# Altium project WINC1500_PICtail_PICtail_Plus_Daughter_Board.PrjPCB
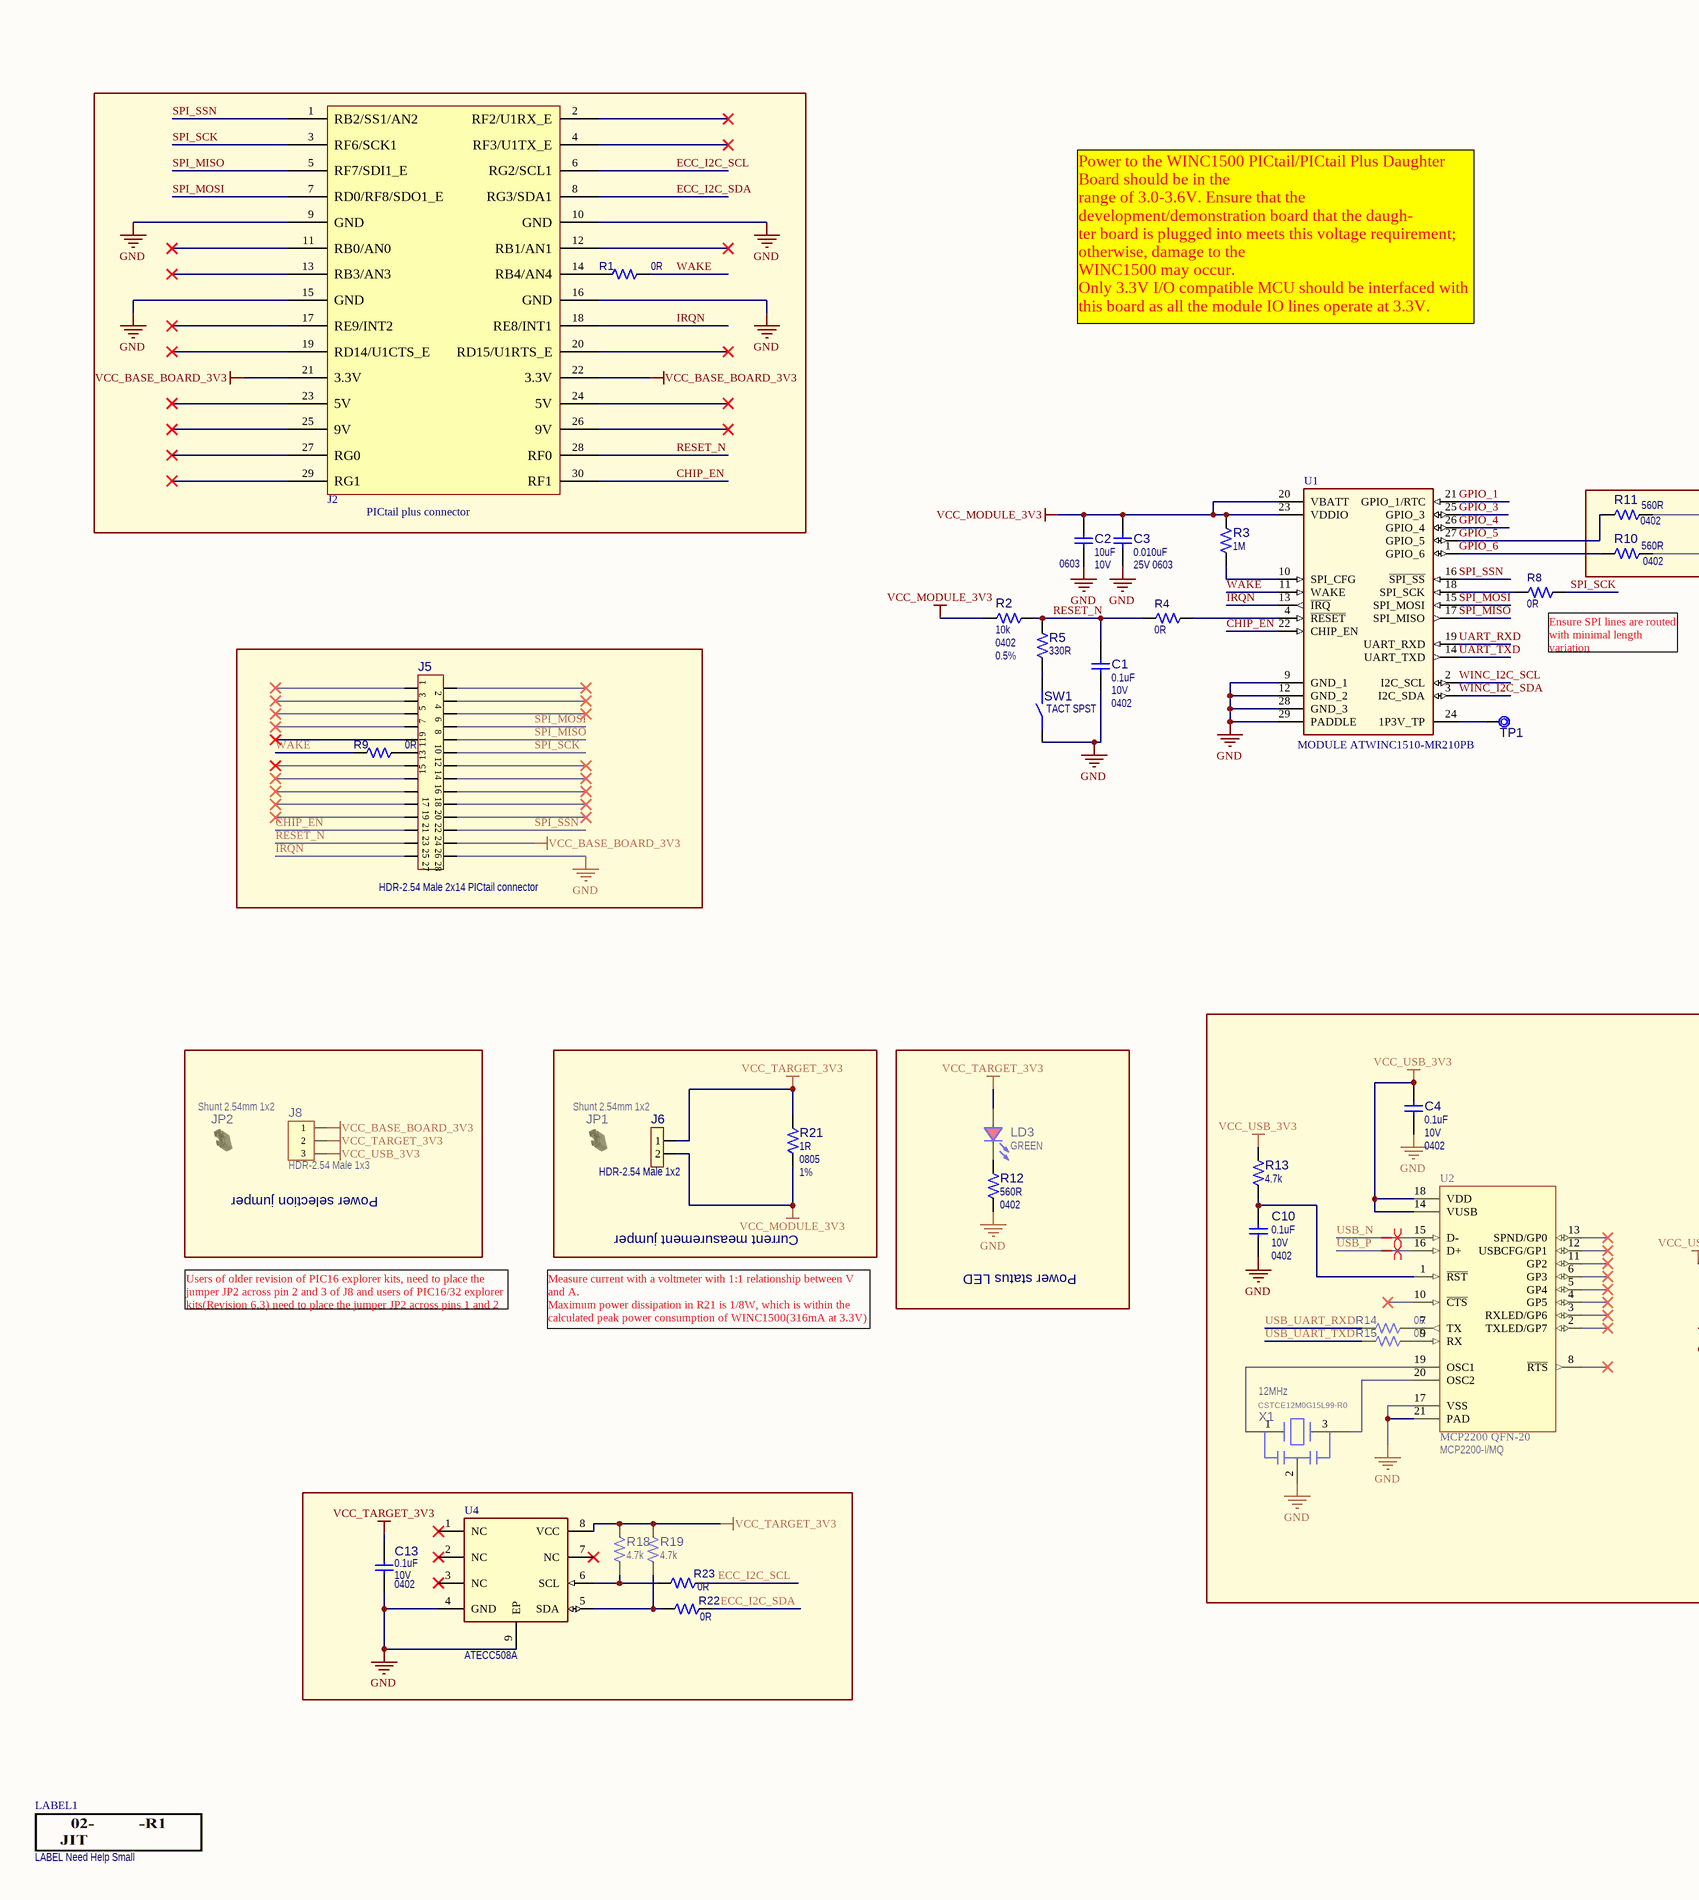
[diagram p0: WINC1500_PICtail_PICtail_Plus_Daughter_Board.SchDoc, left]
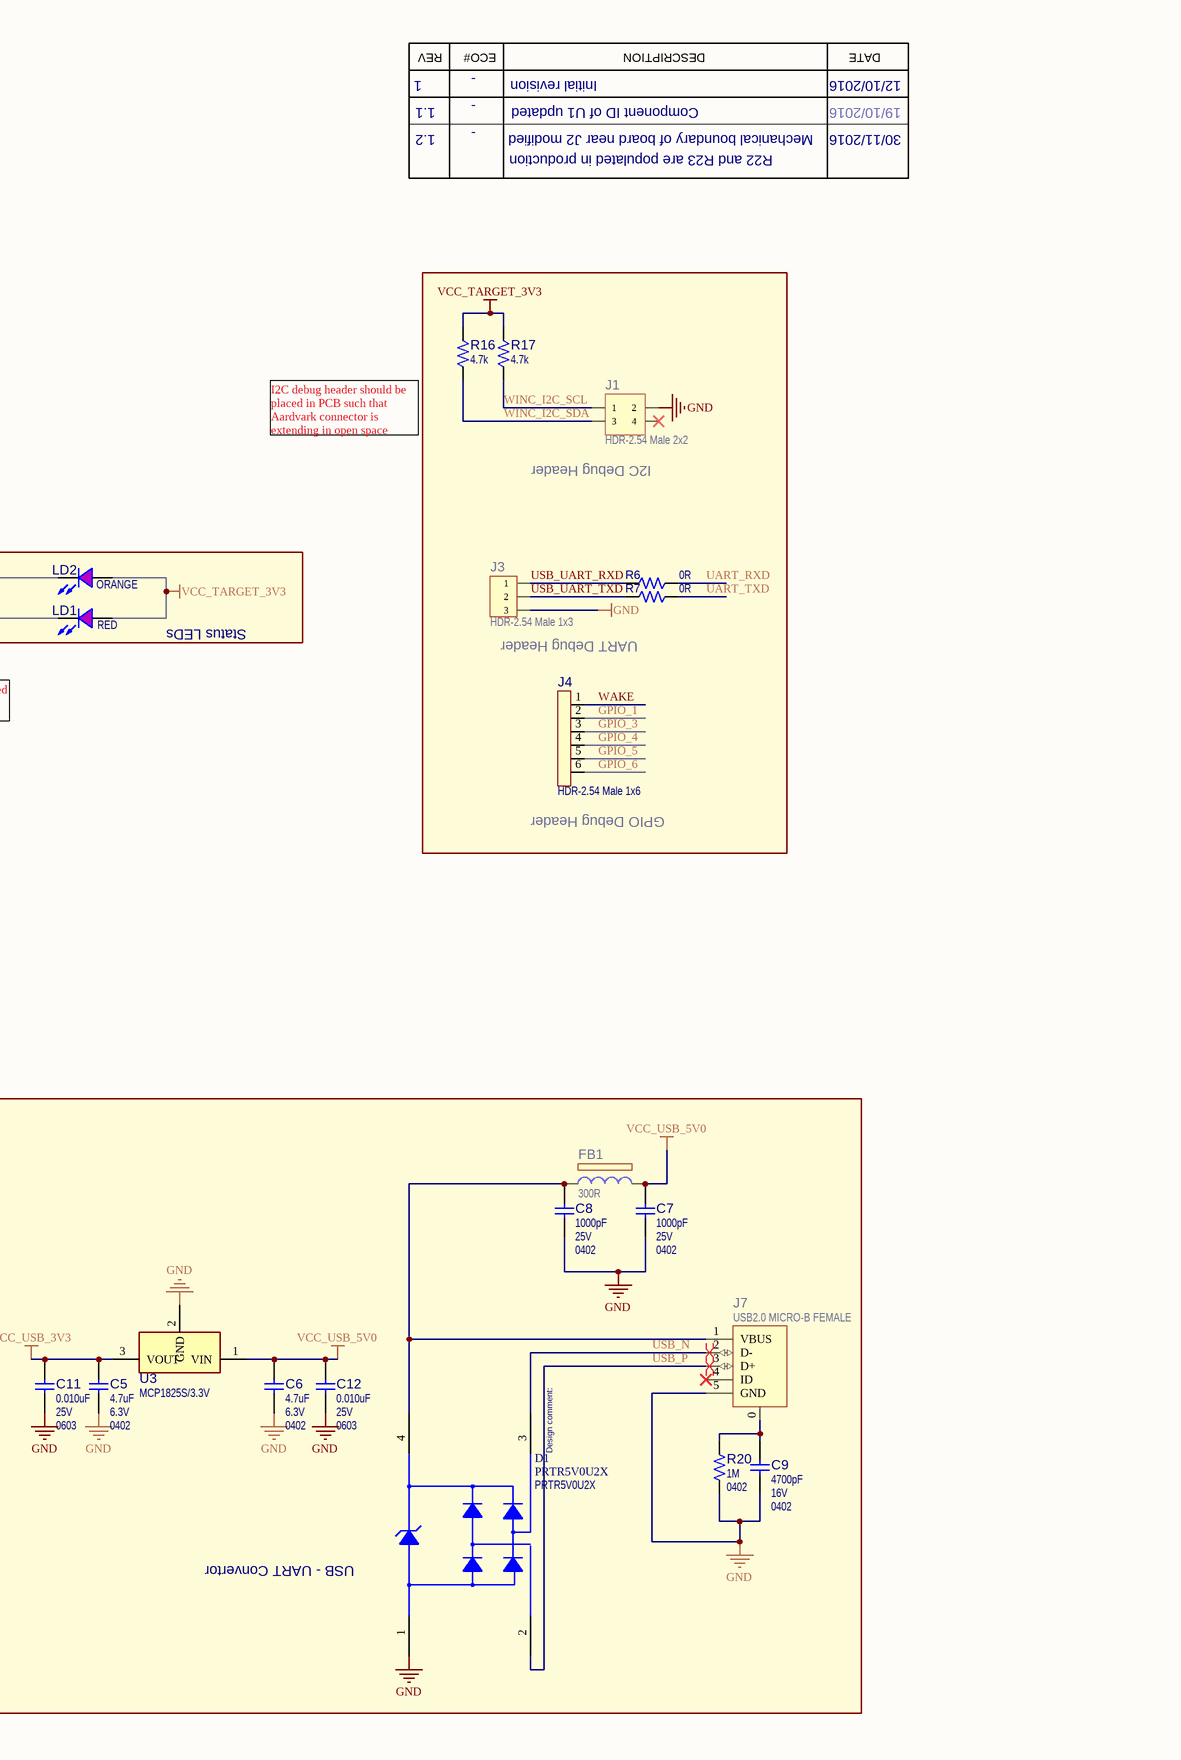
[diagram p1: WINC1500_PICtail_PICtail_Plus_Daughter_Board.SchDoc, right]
ProjectTitle: WINC1500 PICtail/PICtail Plus Daughter Board; ProjectRevisionSCH: 1.2; ProjectRevisionFAB: 1.2; ProjectRevisionASSY: 1.2; ProjectRevisionART: 1.2; ProjectPartNumber: AC164156; ProjectEngineer: Arun karthik; ProjectDrawnBy: Arun karthik; ProjectBoardNumber: 10608
1 sheet, 60 parts. Net scope: global (net labels, ports and power ports of the same name join across sheets).
Board file: WINC1500_PICtail_PICtail_Plus_Daughter_Board.PcbDoc

## Sheet WINC1500_PICtail_PICtail_Plus_Daughter_Board.SchDoc: WINC1500 PICtail
size C; Author: Arun karthik; CompanyName: Microchip Technology Inc.; DrawnBy: Arun karthik; Engineer: Arun karthik; Organization: Microchip Technology; Address1: 2355 West Chandler Blvd.; Address2: Chandler, AZ  85224; Address4: USA; DocumentNumber: 1; Revision: 1.2; SheetNumber: 1; SheetTotal: 1; SheetTitle: WINC1500 PICtail; ProjectDrawnby: Arun karthik; ProjectEngineer: Arun karthik; ProjectRevisionSCH: 1.2; ProjectBoardNumber: 10608; ProjectPartNumber: AC164156; ProjectTitle: WINC1500 PICtail/PICtail Plus Board

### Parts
?  (no value)  (graphical)
C1  value 0.1uF  Voltage: 10V  Package: 0402  [CAP_C_0402]  (hidden comment: Capacitor NP)
C2  value 10uF  Voltage: 10V  Package: 0603  [CAP_C_0603]  (hidden comment: Capacitor NP)
C3  value 0.010uF  Voltage: 25V  Package: 0603  [CAP_C_0603]  (hidden comment: Capacitor NP)
C4  value 0.1uF  Voltage: 10V  Package: 0402  [CAP_C_0402]  (hidden comment: Capacitor NP)
C5  value 4.7uF  Voltage: 6.3V  Package: 0402  [CAP_C_0402]  (hidden comment: Capacitor NP)
C6  value 4.7uF  Voltage: 6.3V  Package: 0402  [CAP_C_0402]  (hidden comment: Capacitor NP)
C7  value 1000pF  Voltage: 25V  Package: 0402  [CAP_C_0402]  (hidden comment: Capacitor NP)
C8  value 1000pF  Voltage: 25V  Package: 0402  [CAP_C_0402]  (hidden comment: Capacitor NP)
C9  value 4700pF  Voltage: 16V  Package: 0402  [CAP_C_0402]  (hidden comment: Capacitor NP)
C10  value 0.1uF  Voltage: 10V  Package: 0402  [CAP_C_0402]  (hidden comment: Capacitor NP)
C11  value 0.010uF  Voltage: 25V  Package: 0603  [CAP_C_0603]  (hidden comment: Capacitor NP)
C12  value 0.010uF  Voltage: 25V  Package: 0603  [CAP_C_0603]  (hidden comment: Capacitor NP)
C13  value 0.1uF  Voltage: 10V  Package: 0402  [CAP_C_0402]  (hidden comment: Capacitor NP)
D1  PRTR5V0U2X  [SOT-143]
FB1  value 300R  [IND_C_0805]  (hidden comment: Ferrite Bead)
J1  value HDR-2.54 Male 2x2  [HDR_M_2.54_2x2]  (hidden comment: Header 2x2)
J2  PICtail plus connector  [CON_EDGE-CARD_PCB_RA_PICTAIL_PLUS_30A_Alternate1]  (no BOM)
J3  value HDR-2.54 Male 1x3  [HDR_M_2.54_1x3]  (hidden comment: Header 1x3)
J4  value HDR-2.54 Male 1x6  [HDR_M_2.54_1x6]  (hidden comment: Header 1x6)
J5  value HDR-2.54 Male 2x14 PICtail connector  [HDR_M_2.54_2x14_RA]  (hidden comment: Header 2x14)
J6  value HDR-2.54 Male 1x2  [HDR_M_2.54_1x2]  (hidden comment: Header 1x2)
J7  value USB2.0 MICRO-B FEMALE  [CON_USB_Micro-AB_SMD_TH_RA_FCI_10118194-0001LF]  (hidden comment: CON USB2.0 Mini_Micro)
J8  value HDR-2.54 Male 1x3  [HDR_M_2.54_1x3]  (hidden comment: Header 1x3)
JP1  value Shunt 2.54mm 1x2  [Jumper_Mechanical]  (hidden comment: Jumper Mechanical)
JP2  value Shunt 2.54mm 1x2  [Jumper_Mechanical]  (hidden comment: Jumper Mechanical)
LABEL1  value LABEL Need Help Small  [LABEL_08-00028]  (hidden comment: LABEL_08-00028)
LD1  value RED  [LED_0603_RED]  (hidden comment: LED)
LD2  value ORANGE  [LED_0603_Orange]  (hidden comment: LED)
LD3  value GREEN  [LED_0603_GREEN]  (hidden comment: LED)
R1  value 0R  [RES_C_0402]  (hidden comment: Resistor)
R2  value 10k  Package: 0402  Tolerance: 0.5%  [RES_C_0402]  (hidden comment: Resistor)
R3  value 1M  [RES_C_0402]  (hidden comment: Resistor)
R4  value 0R  [RES_C_0402]  (hidden comment: Resistor)
R5  value 330R  [RES_C_0402]  (hidden comment: Resistor)
R6  value 0R  [RES_C_0402]  (hidden comment: Resistor)
R7  value 0R  [RES_C_0402]  (hidden comment: Resistor)
R8  value 0R  [RES_C_0402]  (hidden comment: Resistor)
R9  value 0R  [RES_C_0402]  (hidden comment: Resistor)
R10  value 560R  Package: 0402  [RES_C_0402]  (hidden comment: Resistor)
R11  value 560R  Package: 0402  [RES_C_0402]  (hidden comment: Resistor)
R12  value 560R  Package: 0402  [RES_C_0402]  (hidden comment: Resistor)
R13  value 4.7k  [RES_C_0402]  (hidden comment: Resistor)
R14  value 0R  [RES_C_0402]  (hidden comment: Resistor)
R15  value 0R  [RES_C_0402]  (hidden comment: Resistor)
R16  value 4.7k  [RES_C_0402]  (hidden comment: Resistor)
R17  value 4.7k  [RES_C_0402]  (hidden comment: Resistor)
R18  value 4.7k  [RES_C_0402]  (hidden comment: Resistor)
R19  value 4.7k  [RES_C_0402]  (hidden comment: Resistor)
R20  value 1M  Package: 0402  [RES_C_0402]  (hidden comment: Resistor)
R21  value 1R  Package: 0805  Tolerance: 1%  [RES_C_0805]  (hidden comment: Resistor)
R22  value 0R  [RES_C_0402]  (hidden comment: Resistor)
R23  value 0R  [RES_C_0402]  (hidden comment: Resistor)
SW1  value TACT SPST  [SW_TACT_SMD_CK_KSR231GLFS]  (hidden comment: Switch 2 Pin)
TP1  Test Point No BOM  [TP_1.2x0.7]  (value not drawn)  (no BOM)
U1  MODULE ATWINC1510-MR210PB  [MOD_ATWINC1500-MR210PB]
U2  MCP2200 QFN-20  value MCP2200-I/MQ  [QFN-20_5X5]
U3  value MCP1825S/3.3V  [SOT-223-3]  (hidden comment: MCP182XS SOT-223-3_DDPAK-3_TO-220-3)
U4  value ATECC508A  [UDFN-8_2X3_EP1.5X1.3]  (hidden comment: ATECC508A UDFN-8)
X1  CSTCE12M0G15L99-R0  value 12MHz  [RESONATOR_CSTCE-G_L3.2W1.3H0.8]

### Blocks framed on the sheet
Status LEDs: LD1 LD2 R10 R11
USB - UART Convertor: C4-C12 D1 FB1 J7 R13-R15 R20 U2 U3 X1
Power selection jumper: J8 JP2
Current measurement jumper: J6 JP1 R21
Power status LED: LD3 R12

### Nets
GND: C1.1 C2.1 C3.1 C4.1 C5.1 C6.2 C7.2 C8.1 C9.1 C10.1 C11.1 C12.1 C13.1 D1.1(GND) J1.2 J2.9(GND) J2.10(GND) J2.15(GND) J2.16(GND) J3.3 J5.28 J7.5(GND) R12.1 R20.1 SW1.1 U1.9(GND_1) U1.12(GND_2) U1.28(GND_3) U1.29(PADDLE) U2.17(VSS) U2.21(PAD) U3.2(GND) U4.4(GND) U4.9(EP) X1.2(GND)
VCC_BASE_BOARD_3V3: J2.21(3.3V) J2.22(3.3V) J5.26 J8.1
VCC_MODULE_3V3: C2.2 C3.2 J6.2 R2.2 R3.2 R21.1 U1.20(VBATT) U1.23(VDDIO)
VCC_TARGET_3V3: C13.2 J6.1 J8.2 LD1.1(A) LD2.1(A) LD3.1(A) R16.2 R17.2 R18.2 R19.2 R21.2 U4.8(VCC)
VCC_USB_3V3: C4.2 C5.2 C11.2 J8.3 R13.2 U2.14(VUSB) U2.18(VDD) U3.3(VOUT)
VCC_USB_5V0: C6.1 C7.1 C12.2 FB1.2 U3.1(VIN)
CHIP_EN: J2.30(RF1) J5.23 U1.22(CHIP_EN)
ECC_I2C_SCL: J2.6(RG2/SCL1) R23.2
ECC_I2C_SDA: J2.8(RG3/SDA1) R22.2
GPIO_1: J4.2 U1.21(GPIO_1/RTC)
GPIO_3: J4.3 U1.25(GPIO_3)
GPIO_4: J4.4 U1.26(GPIO_4)
GPIO_5: J4.5 R11.1 U1.27(GPIO_5)
GPIO_6: J4.6 R10.1 U1.1(GPIO_6)
IRQN: J2.18(RE8/INT1) J5.27 U1.13(~{IRQ})
RESET_N: C1.2 J2.28(RF0) J5.25 R2.1 R4.2 R5.2
SPI_MISO: J2.5(RF7/SDI1_E) J5.10 U1.17(SPI_MISO)
SPI_MOSI: J2.7(RD0/RF8/SDO1_E) J5.8 U1.15(SPI_MOSI)
SPI_SCK: J2.3(RF6/SCK1) J5.12 R8.1
SPI_SSN: J2.1(RB2/SS1/AN2) J5.24 U1.16(~{SPI_SS})
UART_RXD: R6.2 U1.19(UART_RXD)
UART_TXD: R7.2 U1.14(UART_TXD)
USB_N: D1.3(I/O_2) J7.2(D-) U2.15(D-)
USB_P: D1.2(I/O_1) J7.3(D+) U2.16(D+)
USB_UART_RXD: J3.1 R6.1 R14.1
USB_UART_TXD: J3.2 R7.1 R15.1
WAKE: J4.1 R1.2 R9.1 U1.11(WAKE)
WINC_I2C_SCL: J1.1 R17.1 U1.2(I2C_SCL)
WINC_I2C_SDA: J1.3 R16.1 U1.3(I2C_SDA)
NetC8_2: C8.2 D1.4(VCC) FB1.1 J7.1(VBUS)
NetC9_2: C9.2 J7.0(SHLD) R20.2
NetC10_2: C10.2 R13.1 U2.1(~{RST})
NetJ2_14: J2.14(RB4/AN4) R1.1
NetJ5_11: J5.11 R9.2
NetLD1_2: LD1.2(K) R10.2
NetLD2_2: LD2.2(K) R11.2
NetLD3_2: LD3.2(K) R12.2
NetR3_1: R3.1 U1.10(SPI_CFG)
NetR4_1: R4.1 U1.4(~{RESET})
NetR5_1: R5.1 SW1.2
NetR8_2: R8.2 U1.18(SPI_SCK)
NetR14_2: R14.2 U2.7(TX)
NetR15_2: R15.2 U2.9(RX)
NetR18_1: R18.1 R23.1 U4.6(SCL)
NetR19_1: R19.1 R22.1 U4.5(SDA)
NetTP1_1: TP1.1 U1.24(1P3V_TP)
NetU2_19: U2.19(OSC1) X1.1(IN)
NetU2_20: U2.20(OSC2) X1.3(OUT)

Not connected (* = marked no-connect by the designer): J1 4*; J2 2(RF2/U1RX_E)* 4(RF3/U1TX_E)* 11(RB0/AN0)* 12(RB1/AN1)* 13(RB3/AN3)* 17(RE9/INT2)* 19(RD14/U1CTS_E)* 20(RD15/U1RTS_E)* 23(5V)* 24(5V)* 25(9V)* 26(9V)* 27(RG0)* 29(RG1)*; J5 1* 2* 3* 4* 5* 6* 7* 9* 13* 14* 15* 16* 17* 18* 19* 20* 21* 22*; J7 4(ID)*; U2 2(TXLED/GP7)* 3(RXLED/GP6)* 4(GP5)* 5(GP4)* 6(GP3)* 8(~{RTS})* 10(~{CTS})* 11(GP2)* 12(USBCFG/GP1)* 13(SPND/GP0)*; U4 1(NC)* 2(NC)* 3(NC)* 7(NC)*

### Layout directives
differential pair: USB_N, USB_P

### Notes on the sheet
- 1
- REV
- -
- ECO#
- Initial revision
- DESCRIPTION
- DATE
- 12/10/2016
- 1.1
- 1.2
- Component ID of U1 updated
- R22 and R23 are populated in production
- Mechanical boundary of board near J2 modified
- 19/10/2016
- 30/11/2016
- Power to the WINC1500 PICtail/PICtail Plus Daughter Board should be in the
  range of 3.0-3.6V. Ensure that the development/demonstration board that the daugh-
  ter board is plugged into meets this voltage requirement; otherwise, damage to the
  WINC1500 may occur.
  Only 3.3V I/O compatible MCU should be interfaced with this board as all the module IO lines operate at 3.3V.
- (near R16) I2C debug header should be placed in PCB such that Aardvark connector is extending in open space
- (near J1) I2C Debug Header
- UART Debug Header
- (near R8) Ensure SPI lines are routed with minimal length variation
- (near J4) GPIO Debug Header
- Users of older revision of PIC16 explorer kits, need to place the jumper JP2 across pin 2 and 3 of J8 and users of PIC16/32 explorer kits(Revision 6.3) need to place the jumper JP2 across pins 1 and 2 of J8
- Measure current with a voltmeter with 1:1 relationship between V and A.
  Maximum power dissipation in R21 is 1/8W, which is within the calculated peak power consumption of WINC1500(316mA at 3.3V)

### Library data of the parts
? = Title Block C
C1 C4 C10 C13 = CAP0279: Capacitor; Manufacturer 1: KEMET; Manufacturer Part Number 1: C0402C104K8PACTU; Description_: CAP CER 0.1uF 10V 10% X5R SMD 0402; Dev Tools Status: Production; Tolerance: 10%; Temperature Coeffcient: X5R; Type: Ceramic; Populated: Yes
C2 = CAP0542: Capacitor; Manufacturer 1: Panasonic; Manufacturer Part Number 1: ECJ-1VB1A106M; Description_: CAP CER 10uF 10V 20% X5R SMD 0603; Dev Tools Status: Production; Tolerance: 20%; Temperature Coeffcient: X5R; Type: Ceramic; Populated: Yes
C3 C11 C12 = CAP0602: Capacitor; Manufacturer 1: Yageo; Manufacturer Part Number 1: CC0603KRX7R8BB103; Description_: CAP CER 0.010uF 25V 10% X7R SMD 0603; Dev Tools Status: Production; Tolerance: 10%; Temperature Coeffcient: X7R; Type: Ceramic; Populated: Yes
C5 C6 = CAP1207: Capacitor; Manufacturer 1: Murata; Manufacturer Part Number 1: GRM155R60J475ME47D; Description_: CAP CER 4.7uF 6.3V 20% X5R SMD 0402; Dev Tools Status: Production; Tolerance: 20%; Temperature Coeffcient: X5R; Type: Ceramic; Owner: Tad Ahlvers; Populated: YES
C7 C8 = CAP0566: Capacitor; Manufacturer 1: TDK; Manufacturer Part Number 1: C1005C0G1E102J; Description_: CAP CER 1000pF 25V 5% C0G SMD 0402; Dev Tools Status: Production; Tolerance: 5%; Temperature Coeffcient: C0G; Type: Ceramic; Populated: Yes
C9 = CAP1479: Capacitor; Manufacturer 1: Murata Electronics North America; Manufacturer Part Number 1: GRM155R71C472KA01D; Description_: CAP CER 4700pF 16V 10% X7R SMD 0402; Dev Tools Status: Design; Tolerance: 10%; Temperature Coeffcient: X7R; Type: Ceramic; Owner: Sorin Stanoaia; Populated: YES
D1 = DIODE1279: Manufacturer 1: NXP Semiconductors; Manufacturer Part Number 1: PRTR5V0U2X,215; Description_: DIO TVS PRTR5V0U2X 5.5V SMD SOT-143; Dev Tools Status: Design; Type: TVS; Reverse Voltage: 5.5V; Owner: Razvan Cristescu; Populated: YES
FB1 = IND1291: Manufacturer 1: Laird-Signal Integrity Products; Manufacturer Part Number 1: MI0805L301R-10; Description_: FERRITE 300R@100MHz 2A SMD 0805; Dev Tools Status: Production; Owner: Gabor Bihari; DCR: 0.1R; RMS Current: 2A; Test Frequency: 100MHz; Populated: YES
J1 = CON0057: Manufacturer 1: Samtec; Manufacturer Part Number 1: HTSW-102-07-G-D; Description_: CON HDR-2.54 Male 2x2 Gold 5.84MH TH VERT; Dev Tools Status: Production; Current: 3A; Populated: No
J2 = CON1387: Description_: CON_EDGE-CARD_PCB_RA_PICTAIL_PLUS_30A_0B; Dev Tools Status: Design; Owner: Duane Burt; Populated: YES
J3 = CON0465: Manufacturer 1: Samtec; Manufacturer Part Number 1: TSW-103-07-T-S; Description_: CON HDR-2.54 Male 1x3 Tin 5.84MH TH VERT; Dev Tools Status: Production; Populated: No
J4 = CON0438: Manufacturer 1: Sullins; Manufacturer Part Number 1: PEC06SAAN; Description_: CON HDR-2.54 Male 1x6 Tin 5.84MH TH VERT; Dev Tools Status: Production; Current: 3A; Populated: No
J5 = CON0174: Manufacturer 1: Sullins; Manufacturer Part Number 1: PBC14DBDN; Description_: CON HDR-2.54 Male 2x14 Gold 5.84MH TH R/A; Dev Tools Status: Production; Owner: Duane Burt; Current: 3A; Populated: YES
J6 = CON1108: Manufacturer 1: FCI; Manufacturer Part Number 1: 77311-118-02LF; Description_: CON HDR-2.54 Male 1x2 Gold 5.84MH TH VERT; Dev Tools Status: Production; Owner: Bogdan P (M91398); Populated: Yes
J7 = CON1383: Connector USB Mini; Manufacturer 1: FCI; Manufacturer Part Number 1: 10118194-0001LF; Description_: CON USB2.0 MICRO-B FEMALE TH/SMD R/A; Dev Tools Status: Production; Owner: Jamus Griego; Populated: YES
J8 = CON0465: Manufacturer 1: Samtec; Manufacturer Part Number 1: TSW-103-07-T-S; Description_: CON HDR-2.54 Male 1x3 Tin 5.84MH TH VERT; Dev Tools Status: Production; Populated: Yes
JP1 JP2 = HW1006: Manufacturer 1: 3M; Manufacturer Part Number 1: 969102-0000-DA; MCHP-ID: HW1006; Description_: MECH HW JUMPER 2.54mm 1x2; Dev Tools Status: Production; Owner: Mike Ragsdale; Populated: YES
LABEL1 = LABEL_08-00028: Description_: LABEL, ASSY W/REV LEVEL (SMALL MODULES) PER MTS-0002; Dev Tools Status: Production; Populated: MECH
LD1 = DIODE1058: Manufacturer 1: Lite-On; Manufacturer Part Number 1: LTST-C190EKT; Description_: DIO LED RED 2V 30mA 2mcd Clear SMD 0603; Dev Tools Status: Production; Type: LED Single; Forward Current: 30mA; Power: 100mW; Reverse Current: 100uA; Reverse Voltage: 5V; Owner: Tad Ahlvers; Populated: YES
LD2 = LED0123: Manufacturer 1: Lite-On; Manufacturer Part Number 1: LTST-C190KFKT; Description_: DIO LED ORANGE 2V 30mA 90mcd Clear SMD 0603; Dev Tools Status: Production; Type: LED Single; Forward Current: 30mA; Power: 75mW; Reverse Current: 100uA; Reverse Voltage: 5V; Populated: Yes
LD3 = LED0113: Manufacturer 1: Lite-On; Manufacturer Part Number 1: LTST-C190GKT; Description_: DIO LED GREEN 2.1V 30mA 6mcd Clear SMD 0603; Dev Tools Status: Production; Type: LED Single; Forward Current: 30mA; Power: 100mW; Reverse Current: 100uA; Reverse Voltage: 5V; Populated: Yes
R1 R4 R6-R9 R14 R15 = RSMT0730: Manufacturer 1: Panasonic; Manufacturer Part Number 1: ERJ-2GE0R00X; Description_: RES TKF 0R SMD 0402; Dev Tools Status: Production; Power: 1/10W; Populated: Yes
R2 = RES1012: Manufacturer 1: SUSUMU; Manufacturer Part Number 1: RR0510P-103-D; Description_: RES TF 10k 0.5% 1/16W SMD 0402; Dev Tools Status: Production; Voltage: 25V; Temperature Coeffcient: 25ppm/C; Power: 1/16W; Owner: Tad Ahlvers; Populated: YES
R3 = RES1019: Manufacturer 1: Yageo; Manufacturer Part Number 1: RC0402JR-071ML; Tolerance: 5%; Description_: RES TKF 1M 5% 1/16W SMD 0402; Dev Tools Status: Production; Voltage: 50V; Temperature Coeffcient: 100ppm/C; Power: 1/16W; Owner: Tad Ahlvers; Populated: YES
R5 = RES1385: Manufacturer 1: Panasonic Electronic Components; Manufacturer Part Number 1: ERJ-2GEJ331X; Tolerance: 5%; Description_: RES TKF 330R 5% 1/10W SMD 0402; Dev Tools Status: Production; Voltage: 100V; Temperature Coeffcient: 200ppm/C; Circuit Type: Isolated; Power: 1/10W; Owner: Jairuz Agang-ang; Populated: No
R10-R12 = RSMT0731: Manufacturer 1: Panasonic; Manufacturer Part Number 1: ERJ-2GEJ561X; Description_: RES TKF 560R 5% 1/10W SMD 0402; Dev Tools Status: Production; Voltage: 50V; Temperature Coeffcient: 200ppm/C; Power: 1/10W; Populated: Yes
R13 R16-R19 = RES1462: Manufacturer 1: KOA Speer; Manufacturer Part Number 1: RK73H1ETTP4701F; Description_: RES TKF 4.7K 1% 1/10W 0402; Dev Tools Status: Production; Voltage: 50V; Temperature Coeffcient: 100ppm/C; Circuit Type: Isolated; Power: 1/10W; Owner: Stephen Humberd; Populated: YES
R20 = RES1019: Manufacturer 1: Yageo; Manufacturer Part Number 1: RC0402JR-071ML; Description_: RES TKF 1M 5% 1/16W SMD 0402; Dev Tools Status: Production; Voltage: 50V; Temperature Coeffcient: 100ppm/C; Power: 1/16W; Owner: Tad Ahlvers; Populated: YES
R21 = RSMT0519: Manufacturer 1: Panasonic; Manufacturer Part Number 1: ERJ-6RQF1R0V; Description_: RES TKF 1R 1% 1/8W SMD 0805; Dev Tools Status: Production; Temperature Coeffcient: 200ppm/C; Power: 1/8W; Populated: Yes
R22 R23 = RSMT0730: Manufacturer 1: Panasonic; Manufacturer Part Number 1: ERJ-2GE0R00X; Description_: RES TKF 0R SMD 0402; Dev Tools Status: Production; Power: 1/10W; Populated: YES
SW1 = SWITCH1023: Switch; Manufacturer 1: C&K Components; Manufacturer Part Number 1: KSR231GLFS; Description_: SWITCH TACT SPST 32V 50mA KSR231GLFS SMD; Dev Tools Status: Production; Owner: Tad Ahlvers; Voltage: 32V; Current: 50mA; Populated: No
TP1 = CON1128: Test Point; Value: TP PAD PCB 1.2x0.7; Description_: CON TP PAD PCB 1.2x0.7 TH; Dev Tools Status: Production; Owner: Bogdan P (M91398); Populated: Yes
U1 = MIC6777: Manufacturer 1: Atmel; Description_: MCHP RF WI-FI 802.11b/g/n ATWINC1510 MODULE-28; Dev Tools Status: Design; Owner: Razvan Cristescu; Populated: YES
U2 = MIC6326: USB 2.0 to UART Protocol Conv with GPIO QFN20; Manufacturer: Microchip Technology; Number of Channels: 8; Voltage: 3V ~ 5.5V; Description_: MCHP INTERFACE USB UART MCP2200-I/MQ QFN-20; MAPS Description: USB to UART Protocol Converter; Dev Tools Status: Production; Owner: Jamus Griego; MPC: LEAG17P8X026; LeadContent: Pb-FREE; PackingMedia: TUBE; Stage: REL; LeadCount: 20; PackageWidth: 5x5x0.9mm; ForceMinOrderQtyMult: False; MinOrderQty: 5; TempRange: -40C to +85C; tblDeviceFamilyID: 2705; OperatingVoltageMin: 3.0; OperatingVoltageMax: 5.5; PHY: Yes; EEPROM: 256; USB: Full Speed; usbcompliant: USB 2.0; TxBuffers: 128; oscillator: External
U3 = MIC0763: LDO; Manufacturer 1: Microchip; Manufacturer Part Number 1: MCP1825ST-3302E/DB; Description_: MCHP ANALOG LDO 3.3V MCP1825ST-3302E/DB SOT-223-3; Symbol: MCP1825S SOT-223-3; MAPS Description: 500mA LOW VOLTAGE, LOW IQ LDO; Dev Tools Status: Production; MPC: GEAT1YF6XB33; LeadContent: Pb-FREE; PackingMedia: T/R; Stage: REL; LeadCount: 3; ForceMinOrderQtyMult: True; MinOrderQty: 50; TempRange: -40C to +125C; tblDeviceFamilyID: 1826; Populated: Yes
U4 = IC1305: Manufacturer 1: Atmel; Manufacturer Part Number 1: ATECC508A-MAHDA-T; MCHP-ID: IC1305; Description_: IC INTERFACE ATECC508A UDFN-8; Dev Tools Status: Design; Owner: Razvan Cristescu; Populated: YES
X1 = OSC1027: Resonator; Manufacturer 1: Murata; Description_: RESONATOR 12MHz 0.1% SMD CSTCE-G; Dev Tools Status: Production; Owner: Bogdan P (M91398); Tolerance: 0.1%; Populated: YES

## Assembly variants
Production: not fitted J1 J3 J4 R5 SW1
